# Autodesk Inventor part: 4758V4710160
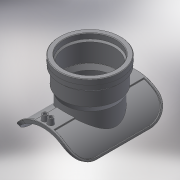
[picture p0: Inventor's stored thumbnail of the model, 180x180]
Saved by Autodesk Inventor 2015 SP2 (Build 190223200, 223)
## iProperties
Created: 2017-08
Part Number: 4758V4710160
Material: Generic
Description: PLASSON WASTEWATER SADDLE 560-710X160 PVC/PP ADAPTOR INLET
Document SubType Name: Modeling
Designer: Кирилл
Density: 1 g/cm^3
Appearance: Default
Author: Кирилл
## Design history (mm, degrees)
derived "4758V4.ipt"
feature "Solid1::4758V4.ipt"
feature "Solid2::4758V4.ipt"
feature "Solid3::4758V4.ipt"
tag "TaggingFeature1"
body "Solid1"
other parameters: "d1" = 277, "d2" = 738.4, "d4" = 0, "d5" = 83.1, "d6" = 8, "d7" = 15 deg, "d8" = 7.5 deg, "d10" = 0, "d11" = 461.5, "d38" = 3.55, "d40" = 381, "d41" = 15, "d42" = 130.5, "d43" = 17.6, "d44" = 8.8, "d46" = 5 deg, "d47" = 4, "d49" = 4, "d51" = 14, "d52" = 0, "d53" = 3, "d54" = 0, "d57" = 0.5, "d59" = 16, "d60" = 5.6, "d61" = 40 deg, "d62" = 152, "d63" = 156.8, "d64" = 144, "d65" = 155 deg, "d66" = 125, "d68" = 188.1, "d69" = 45 deg, "d70" = 175, "d72" = 7.5, "d75" = 0, "d77" = 0, "d78" = 1.6, "d81" = 37.5, "B_" = 277, "H_" = 125, "d71" = 7.5
